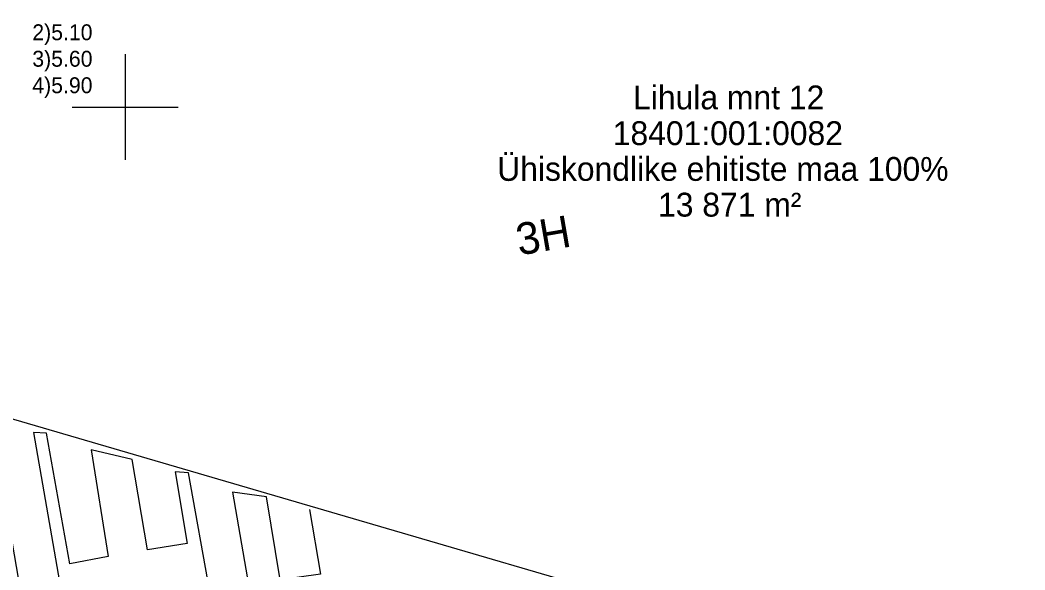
# Model space of a CAD drawing. Extents: x 473307 to 473719, y 6532843 to 6533381.
# Drawn here: x 473546.03 to 473584.01, y 6532982.52 to 6533003.28 of the extents above; entities that cross this region are included whole.
import ezdxf

# ---------------------------------------------------------------- set-up
doc = ezdxf.new("R2010")
doc.units = 0
for name, color, linetype in [('Default', 7, 'Continuous'), ('HOONE', 7, 'Continuous'), ('PIIR', 7, 'Continuous'), ('SKKAEV_NR', 7, 'Continuous'), ('TEE', 7, 'Continuous'), ('VORK', 7, 'Continuous')]:
    doc.layers.add(name, color=color, linetype=linetype)

# ---------------------------------------------------------------- blocks, each defined once
blk = doc.blocks.new('VKORIS')
at = {"layer": 'Default'}
for p, q in [((0, 4), (0, -4)), ((-4, 0), (4, 0))]:
    blk.add_line(p, q, dxfattribs=at)

msp = doc.modelspace()

# ---------------------------------------------------------------- linework, layer by layer
at = {"layer": 'HOONE'}
msp.add_lwpolyline([(473585.831, 6533013.369), (473574.881, 6533011.486), (473566.132, 6533009.962), (473540.511, 6533005.576), (473543.395, 6532988.91), (473585.455, 6532976.623), (473588.828, 6532956.753), (473587.886, 6532956.595), (473589.164, 6532949.286), (473629.221, 6532956.166), (473626.335, 6532972.834), (473619.836, 6532974.765), (473602.305, 6532979.874), (473597.625, 6532979.18), (473590.334, 6532981.418), (473586.157, 6533005.917), (473587.084, 6533006.076)], close=True, dxfattribs=at)
at = {"layer": 'TEE'}
msp.add_lwpolyline([(473556.963, 6532984.802), (473556.963, 6532984.802), (473556.963, 6532984.802), (473556.963, 6532984.802), (473557.385, 6532982.357), (473555.863, 6532982.14), (473555.342, 6532985.275), (473554.052, 6532985.454), (473554.673, 6532981.893), (473553.208, 6532981.623), (473552.392, 6532986.183), (473551.893, 6532986.227), (473552.341, 6532983.523), (473550.847, 6532983.274), (473550.268, 6532986.692), (473548.72, 6532987.053), (473549.36, 6532983.022), (473547.91, 6532982.748), (473547.02, 6532987.68), (473546.53, 6532987.705), (473547.752, 6532980.694), (473546.271, 6532980.446), (473544.878, 6532988.45), (473543.56, 6532988.745)], dxfattribs=at)

# ---------------------------------------------------------------- block references
at = {"layer": 'VORK', "xscale": 0.5, "yscale": 0.5}
msp.add_blockref('VKORIS', (473550, 6533000), dxfattribs=at)

# ---------------------------------------------------------------- texts
at = {"layer": 'HOONE'}
msp.add_text('3H', height=1.2, rotation=9.8418, dxfattribs=at).set_placement((473564.891, 6532994.389))
at = {"layer": 'PIIR'}
for s, p in [('Lihula mnt 12', (473569.199, 6532999.912)), ('18401:001:0082', (473568.429, 6532998.562)), ('Ühiskondlike ehitiste maa 100%', (473564.063, 6532997.212)), ('13 871 m²', (473570.142, 6532995.862))]:
    msp.add_text(s, height=0.9, dxfattribs=at).set_placement(p)
at = {"layer": 'SKKAEV_NR'}
for s, p in [('2)5.10', (473546.49, 6533002.522)), ('3)5.60', (473546.49, 6533001.522)), ('4)5.90', (473546.49, 6533000.522))]:
    msp.add_text(s, height=0.6, dxfattribs=at).set_placement(p)

doc.saveas('drawing.dxf')
